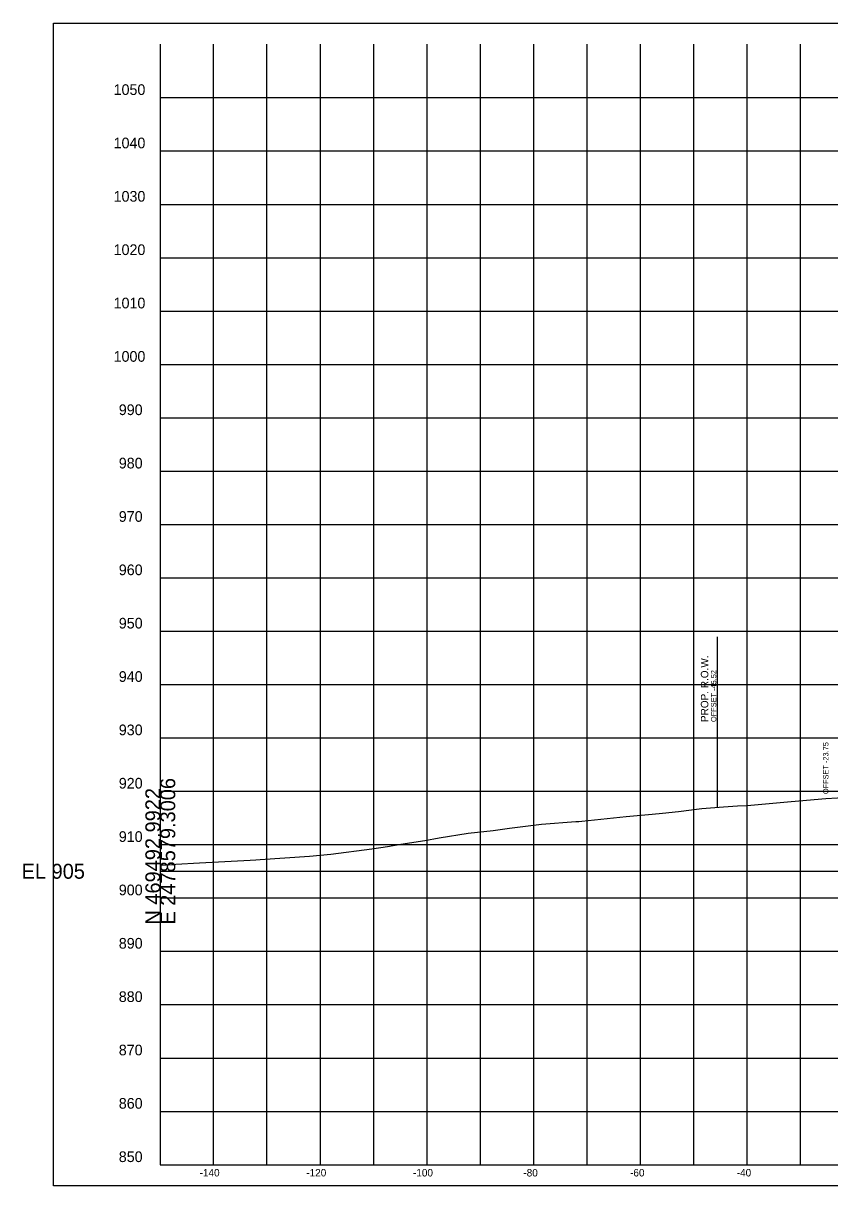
# Model space of a CAD drawing. Extents: x -26 to 2478923, y -10 to 469990.
# Drawn here: x -25.7 to 125.5, y 7441.1 to 7658.9 of the extents above; entities that cross this region are included whole.
import ezdxf

# ---------------------------------------------------------------- set-up
doc = ezdxf.new("R2010")
doc.units = 0
for name, color, linetype in [('DESIGN - ROW - Right-of-Way and Easement Labels', 7, 'Continuous'), ('DESIGN - ROW - Right-of-Way Linework', 7, 'Continuous'), ('DESIGN - SHEET - Corner Text', 7, 'Continuous'), ('DESIGN - SHEET - Light Grid', 7, 'Continuous'), ('DESIGN - SHEET - Linework', 7, 'Continuous'), ('DESIGN - SHEET - Plot Shape', 7, 'Continuous'), ('DESIGN - TYPICAL - Slope Tie Text', 7, 'Continuous'), ('SURVEY - GROUND - Top of Ground', 7, 'Continuous')]:
    doc.layers.add(name, color=color, linetype=linetype)

msp = doc.modelspace()

# ---------------------------------------------------------------- linework, layer by layer
at = {"layer": 'DESIGN - ROW - Right-of-Way Linework'}
msp.add_line((104.48, 7511.97), (104.48, 7543.97), dxfattribs=at)
at = {"layer": 'DESIGN - SHEET - Light Grid'}
msp.add_line((0, 7500), (150, 7500), dxfattribs=at)
at = {"layer": 'DESIGN - SHEET - Linework'}
for p, q in [((10, 7445), (10, 7655)), ((10, 7445), (10, 7655)), ((10, 7445), (10, 7655)), ((10, 7445), (10, 7655)), ((20, 7445), (20, 7655)), ((20, 7445), (20, 7655)), ((20, 7445), (20, 7655)), ((20, 7445), (20, 7655)), ((30, 7445), (30, 7655)), ((30, 7445), (30, 7655)), ((30, 7445), (30, 7655)), ((30, 7445), (30, 7655)), ((40, 7445), (40, 7655)), ((40, 7445), (40, 7655)), ((40, 7445), (40, 7655)), ((40, 7445), (40, 7655)), ((50, 7445), (50, 7655)), ((50, 7445), (50, 7655)), ((50, 7445), (50, 7655)), ((50, 7445), (50, 7655)), ((60, 7445), (60, 7655)), ((60, 7445), (60, 7655)), ((60, 7445), (60, 7655)), ((60, 7445), (60, 7655)), ((70, 7445), (70, 7655)), ((70, 7445), (70, 7655)), ((70, 7445), (70, 7655)), ((70, 7445), (70, 7655)), ((80, 7445), (80, 7655)), ((80, 7445), (80, 7655)), ((80, 7445), (80, 7655)), ((80, 7445), (80, 7655)), ((90, 7445), (90, 7655)), ((90, 7445), (90, 7655)), ((90, 7445), (90, 7655)), ((90, 7445), (90, 7655)), ((100, 7445), (100, 7655)), ((100, 7445), (100, 7655)), ((100, 7445), (100, 7655)), ((100, 7445), (100, 7655)), ((110, 7445), (110, 7655)), ((110, 7445), (110, 7655)), ((110, 7445), (110, 7655)), ((110, 7445), (110, 7655)), ((120, 7445), (120, 7655)), ((120, 7445), (120, 7655)), ((120, 7445), (120, 7655)), ((120, 7445), (120, 7655)), ((0, 7645), (300, 7645)), ((0, 7645), (300, 7645)), ((0, 7645), (300, 7645)), ((0, 7645), (300, 7645)), ((0, 7635), (300, 7635)), ((0, 7635), (300, 7635)), ((0, 7635), (300, 7635)), ((0, 7635), (300, 7635)), ((0, 7625), (300, 7625)), ((0, 7625), (300, 7625)), ((0, 7625), (300, 7625)), ((0, 7625), (300, 7625)), ((0, 7615), (300, 7615)), ((0, 7615), (300, 7615)), ((0, 7615), (300, 7615)), ((0, 7615), (300, 7615)), ((0, 7605), (300, 7605)), ((0, 7605), (300, 7605)), ((0, 7605), (300, 7605)), ((0, 7605), (300, 7605)), ((0, 7595), (300, 7595)), ((0, 7595), (300, 7595)), ((0, 7595), (300, 7595)), ((0, 7595), (300, 7595)), ((0, 7585), (300, 7585)), ((0, 7585), (300, 7585)), ((0, 7585), (300, 7585)), ((0, 7585), (300, 7585)), ((0, 7575), (300, 7575)), ((0, 7575), (300, 7575)), ((0, 7575), (300, 7575)), ((0, 7575), (300, 7575)), ((0, 7565), (300, 7565)), ((0, 7565), (300, 7565)), ((0, 7565), (300, 7565)), ((0, 7565), (300, 7565)), ((0, 7555), (300, 7555)), ((0, 7555), (300, 7555)), ((0, 7555), (300, 7555)), ((0, 7555), (300, 7555)), ((0, 7545), (300, 7545)), ((0, 7545), (300, 7545)), ((0, 7545), (300, 7545)), ((0, 7545), (300, 7545)), ((0, 7535), (300, 7535)), ((0, 7535), (300, 7535)), ((0, 7535), (300, 7535)), ((0, 7535), (300, 7535)), ((0, 7525), (300, 7525)), ((0, 7525), (300, 7525)), ((0, 7525), (300, 7525)), ((0, 7525), (300, 7525)), ((0, 7515), (300, 7515)), ((0, 7515), (300, 7515)), ((0, 7515), (300, 7515)), ((0, 7515), (300, 7515)), ((0, 7505), (300, 7505)), ((0, 7505), (300, 7505)), ((0, 7505), (300, 7505)), ((0, 7505), (300, 7505)), ((0, 7495), (300, 7495)), ((0, 7495), (300, 7495)), ((0, 7495), (300, 7495)), ((0, 7495), (300, 7495)), ((0, 7485), (300, 7485)), ((0, 7485), (300, 7485)), ((0, 7485), (300, 7485)), ((0, 7485), (300, 7485)), ((0, 7475), (300, 7475)), ((0, 7475), (300, 7475)), ((0, 7475), (300, 7475)), ((0, 7475), (300, 7475)), ((0, 7465), (300, 7465)), ((0, 7465), (300, 7465)), ((0, 7465), (300, 7465)), ((0, 7465), (300, 7465)), ((0, 7455), (300, 7455)), ((0, 7455), (300, 7455)), ((0, 7455), (300, 7455)), ((0, 7455), (300, 7455))]:
    msp.add_line(p, q, dxfattribs=at)
msp.add_lwpolyline([(0, 7655), (0, 7445), (300, 7445), (300, 7655)], dxfattribs=at)
msp.add_lwpolyline([(0, 7655), (0, 7445), (300, 7445), (300, 7655)], dxfattribs=at)
msp.add_lwpolyline([(0, 7655), (0, 7445), (300, 7445), (300, 7655)], dxfattribs=at)
msp.add_lwpolyline([(0, 7655), (0, 7445), (300, 7445), (300, 7655)], dxfattribs=at)
at = {"layer": 'DESIGN - SHEET - Plot Shape'}
msp.add_lwpolyline([(-20, 7658.94), (320, 7658.94), (320, 7441.06), (-20, 7441.06)], close=True, dxfattribs=at)
msp.add_lwpolyline([(-20, 7658.94), (320, 7658.94), (320, 7441.06), (-20, 7441.06)], close=True, dxfattribs=at)
msp.add_lwpolyline([(-20, 7658.94), (320, 7658.94), (320, 7441.06), (-20, 7441.06)], close=True, dxfattribs=at)
msp.add_lwpolyline([(-20, 7658.94), (320, 7658.94), (320, 7441.06), (-20, 7441.06)], close=True, dxfattribs=at)
at = {"layer": 'SURVEY - GROUND - Top of Ground'}
msp.add_lwpolyline([(0, 7501.16), (2.18, 7501.28), (2.52, 7501.3), (2.89, 7501.32), (7.33, 7501.56), (16.84, 7502.08), (17.92, 7502.15), (18.7, 7502.18), (27.96, 7502.81), (31.96, 7503.21), (39.67, 7504.2), (42.61, 7504.67), (45.08, 7505.07), (49.56, 7505.76), (52.25, 7506.28), (57.74, 7507.16), (62.37, 7507.65), (65.46, 7508.06), (71.49, 7508.81), (77.91, 7509.31), (78.48, 7509.36), (79, 7509.41), (87.3, 7510.25), (92.22, 7510.69), (94.13, 7510.91), (97.15, 7511.21), (101.54, 7511.76), (105.56, 7512.05), (108.23, 7512.24), (110.04, 7512.34), (118.29, 7513.08), (124.79, 7513.61), (129.12, 7513.9)], dxfattribs=at)

# ---------------------------------------------------------------- texts
at = {"layer": 'DESIGN - ROW - Right-of-Way and Easement Labels'}
for s, height, p in [('PROP. R.O.W.', 1.4, (102.73, 7527.97)), ('OFFSET -45.52', 1, (104.23, 7527.97))]:
    msp.add_text(s, height=height, rotation=90, dxfattribs=at).set_placement(p)
at = {"layer": 'DESIGN - SHEET - Corner Text'}
for s, height, p in [('1050', 2, (-8.75, 7645.5)), ('1050', 2, (-8.75, 7645.5)), ('1050', 2, (-8.75, 7645.5)), ('1050', 2, (-8.75, 7645.5)), ('1040', 2, (-8.75, 7635.5)), ('1040', 2, (-8.75, 7635.5)), ('1040', 2, (-8.75, 7635.5)), ('1040', 2, (-8.75, 7635.5)), ('1030', 2, (-8.75, 7625.5)), ('1030', 2, (-8.75, 7625.5)), ('1030', 2, (-8.75, 7625.5)), ('1030', 2, (-8.75, 7625.5)), ('1020', 2, (-8.75, 7615.5)), ('1020', 2, (-8.75, 7615.5)), ('1020', 2, (-8.75, 7615.5)), ('1020', 2, (-8.75, 7615.5)), ('1010', 2, (-8.75, 7605.5)), ('1010', 2, (-8.75, 7605.5)), ('1010', 2, (-8.75, 7605.5)), ('1010', 2, (-8.75, 7605.5)), ('1000', 2, (-8.75, 7595.5)), ('1000', 2, (-8.75, 7595.5)), ('1000', 2, (-8.75, 7595.5)), ('1000', 2, (-8.75, 7595.5)), ('990', 2, (-7.78, 7585.5)), ('990', 2, (-7.78, 7585.5)), ('990', 2, (-7.78, 7585.5)), ('990', 2, (-7.78, 7585.5)), ('980', 2, (-7.78, 7575.5)), ('980', 2, (-7.78, 7575.5)), ('980', 2, (-7.78, 7575.5)), ('980', 2, (-7.78, 7575.5)), ('970', 2, (-7.78, 7565.5)), ('970', 2, (-7.78, 7565.5)), ('970', 2, (-7.78, 7565.5)), ('970', 2, (-7.78, 7565.5)), ('960', 2, (-7.78, 7555.5)), ('960', 2, (-7.78, 7555.5)), ('960', 2, (-7.78, 7555.5)), ('960', 2, (-7.78, 7555.5)), ('950', 2, (-7.78, 7545.5)), ('950', 2, (-7.78, 7545.5)), ('950', 2, (-7.78, 7545.5)), ('950', 2, (-7.78, 7545.5)), ('940', 2, (-7.78, 7535.5)), ('940', 2, (-7.78, 7535.5)), ('940', 2, (-7.78, 7535.5)), ('940', 2, (-7.78, 7535.5)), ('930', 2, (-7.78, 7525.5)), ('930', 2, (-7.78, 7525.5)), ('930', 2, (-7.78, 7525.5)), ('930', 2, (-7.78, 7525.5)), ('920', 2, (-7.78, 7515.5)), ('920', 2, (-7.78, 7515.5)), ('920', 2, (-7.78, 7515.5)), ('920', 2, (-7.78, 7515.5)), ('910', 2, (-7.78, 7505.5)), ('910', 2, (-7.78, 7505.5)), ('910', 2, (-7.78, 7505.5)), ('910', 2, (-7.78, 7505.5)), ('900', 2, (-7.78, 7495.5)), ('900', 2, (-7.78, 7495.5)), ('900', 2, (-7.78, 7495.5)), ('900', 2, (-7.78, 7495.5)), ('890', 2, (-7.78, 7485.5)), ('890', 2, (-7.78, 7485.5)), ('890', 2, (-7.78, 7485.5)), ('890', 2, (-7.78, 7485.5)), ('880', 2, (-7.78, 7475.5)), ('880', 2, (-7.78, 7475.5)), ('880', 2, (-7.78, 7475.5)), ('880', 2, (-7.78, 7475.5)), ('870', 2, (-7.78, 7465.5)), ('870', 2, (-7.78, 7465.5)), ('870', 2, (-7.78, 7465.5)), ('870', 2, (-7.78, 7465.5)), ('860', 2, (-7.78, 7455.5)), ('860', 2, (-7.78, 7455.5)), ('860', 2, (-7.78, 7455.5)), ('860', 2, (-7.78, 7455.5)), ('850', 2, (-7.78, 7445.5)), ('850', 2, (-7.78, 7445.5)), ('850', 2, (-7.78, 7445.5)), ('850', 2, (-7.78, 7445.5)), ('-140', 1.4, (7.37, 7442.8)), ('-140', 1.4, (7.37, 7442.8)), ('-140', 1.4, (7.37, 7442.8)), ('-140', 1.4, (7.37, 7442.8)), ('-120', 1.4, (27.37, 7442.8)), ('-120', 1.4, (27.37, 7442.8)), ('-120', 1.4, (27.37, 7442.8)), ('-120', 1.4, (27.37, 7442.8)), ('-100', 1.4, (47.37, 7442.8)), ('-100', 1.4, (47.37, 7442.8)), ('-100', 1.4, (47.37, 7442.8)), ('-100', 1.4, (47.37, 7442.8)), ('-80', 1.4, (68.06, 7442.8)), ('-80', 1.4, (68.06, 7442.8)), ('-80', 1.4, (68.06, 7442.8)), ('-80', 1.4, (68.06, 7442.8)), ('-60', 1.4, (88.06, 7442.8)), ('-60', 1.4, (88.06, 7442.8)), ('-60', 1.4, (88.06, 7442.8)), ('-60', 1.4, (88.06, 7442.8)), ('-40', 1.4, (108.06, 7442.8)), ('-40', 1.4, (108.06, 7442.8)), ('-40', 1.4, (108.06, 7442.8)), ('-40', 1.4, (108.06, 7442.8))]:
    msp.add_text(s, height=height, dxfattribs=at).set_placement(p)
at = {"layer": 'DESIGN - SHEET - Light Grid'}
for s, p in [('E 2478579.3006', (2.8, 7490)), ('N 469492.9922', (0, 7490))]:
    msp.add_text(s, height=2.8, rotation=90, dxfattribs=at).set_placement(p)
msp.add_text('EL 905', height=2.8, dxfattribs=at).set_placement((-26, 7498.6))
at = {"layer": 'DESIGN - TYPICAL - Slope Tie Text'}
msp.add_text('OFFSET -23.75', height=1, rotation=90, dxfattribs=at).set_placement((125.25, 7514.46))

doc.saveas('drawing.dxf')
